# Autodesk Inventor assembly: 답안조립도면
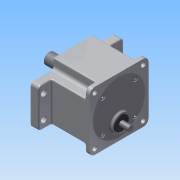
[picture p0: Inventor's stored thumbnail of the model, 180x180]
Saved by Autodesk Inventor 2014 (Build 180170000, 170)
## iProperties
Created: 2015-06
Part Number: 답안조립도면
Document SubType Name: Assembly
Designer: AMC
Author: AMC
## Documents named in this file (12)
- C:\Users\AMC\Desktop\450620V1021\답안조립도면.iam
- C:\Users\AMC\Desktop\450620V1021\본체.ipt
- C:\Users\AMC\Desktop\450620V1021\메인축.ipt
- C:\Users\AMC\Desktop\450620V1021\서브축.ipt
- C:\Users\AMC\Desktop\450620V1021\베어링 608.ipt
- 베어링 608.ipt
- C:\Users\AMC\Desktop\450620V1021\베어링 6003.ipt
- 베어링 6003.ipt
- C:\Users\AMC\Desktop\450620V1021\커버.ipt
- C:\Users\AMC\Desktop\450620V1021\오일실 8x22x7.ipt
- C:\Users\AMC\Desktop\450620V1021\오일실 17x32x8.ipt
- C:\Users\AMC\Desktop\450620V1021\M4x0.5x16.ipt
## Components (4 placed, 1 different names)
1. M4x0.5x12:1
2. M4x0.5x12:2
3. M4x0.5x12:3
4. M4x0.5x12:4
